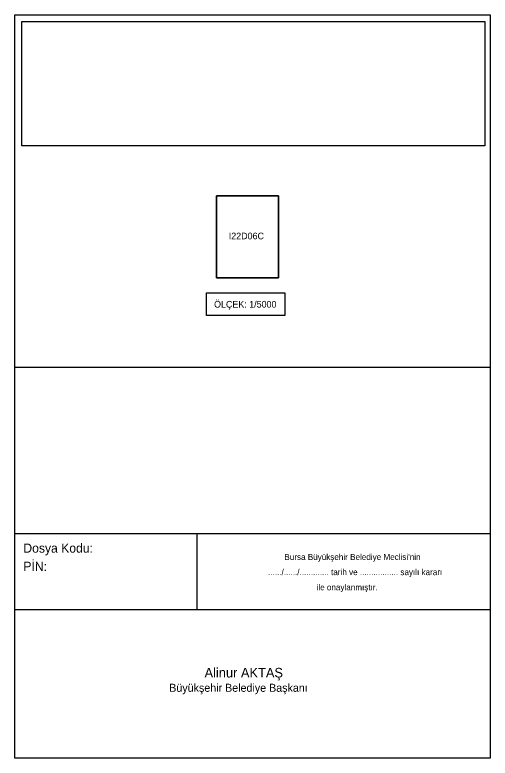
# Model space of a CAD drawing. Extents: x 415376 to 421084, y 4391163 to 4393878.
# Drawn here: x 415376 to 416161, y 4392652 to 4393878 of the extents above; entities that cross this region are included whole.
import ezdxf

# ---------------------------------------------------------------- set-up
doc = ezdxf.new("R2010")
doc.units = 0
doc.layers.add('DEFAULT_', color=7, linetype='Continuous')

msp = doc.modelspace()

# ---------------------------------------------------------------- linework, layer by layer
at = {"layer": 'DEFAULT_'}
for p, q in [((415376.1, 4393203.2), (415376.1, 4393878.1)), ((415376.1, 4393878.1), (416160.7, 4393878.1)), ((416160.7, 4393878.1), (416160.7, 4393203.2)), ((415376.1, 4393296.9), (416160.7, 4393296.9)), ((415376.1, 4392652.2), (415376.1, 4393203.2)), ((416160.7, 4393203.2), (416160.7, 4392652.2)), ((415376.1, 4393022.6), (416160.7, 4393022.6)), ((415676.5, 4393022.6), (415676.5, 4392897.6)), ((415376.1, 4392897.6), (416160.7, 4392897.6)), ((416160.7, 4392652.2), (415376.1, 4392652.2))]:
    msp.add_line(p, q, dxfattribs=at)
for points in [[(416152.1, 4393662.3), (415387.8, 4393662.3), (415387.8, 4393866.9), (416152.1, 4393866.9)], [(415708.9, 4393579.5), (415811.5, 4393579.5), (415811.5, 4393444.3), (415708.9, 4393444.3)], [(415822, 4393382.4), (415692.3, 4393382.4), (415692.3, 4393419.5), (415822, 4393419.5)]]:
    msp.add_lwpolyline(points, close=True, dxfattribs=at)
msp.add_lwpolyline([(415709.2, 4393579.7), (415708.9, 4393579.7), (415708.9, 4393444.5), (415811.5, 4393444.5), (415811.5, 4393579.5), (415709.2, 4393579.5), (415709.2, 4393579.7)], dxfattribs=at)

# ---------------------------------------------------------------- texts
for s, height, p in [('I22D06C', 11, (415729.3, 4393507.9)), ('ÖLÇEK: 1/5000', 11, (415705, 4393395.3)), ('Dosya Kodu:', 15, (415390.2, 4392991.1)), ("Bursa Büyükşehir Belediye Meclisi'nin", 10, (415821.1, 4392979)), ('PİN:', 15, (415390.2, 4392961.1)), ('....../....../............. tarih ve ................. sayılı kararı', 10, (415794.1, 4392954)), ('ile onaylanmıştır.', 10, (415874.2, 4392929)), ('Alinur AKTAŞ', 15.84, (415689.3, 4392785.2)), ('Alinur AKTAŞ', 15.84, (415689.3, 4392785.2)), ('Büyükşehir Belediye Başkanı', 13.2, (415631, 4392761.6)), ('Büyükşehir Belediye Başkanı', 13.2, (415631, 4392761.6))]:
    msp.add_text(s, height=height, dxfattribs=at).set_placement(p)

doc.saveas('drawing.dxf')
